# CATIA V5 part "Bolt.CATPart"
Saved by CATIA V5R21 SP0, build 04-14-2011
Part number: bolt
Bounding box of the stored display mesh (mm): x -86.603 to 86.603, y -100 to 100, z 0 to 450
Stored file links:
  D:\CATIA V5R21 E-RESOURCES\CATIA-V5R21\catia-v5r21-prt\c16-catia-v5r20-prt\Screw Joint-(Fig16-22)\CAT_V5R21_Bolt.CATPart
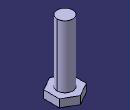
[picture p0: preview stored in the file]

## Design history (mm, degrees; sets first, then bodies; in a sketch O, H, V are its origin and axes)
Body1 (main body)
  Sketch1 on xy-plane, origin (0, 0, 0), H (1, 0, 0), V (0, 1, 0)
    point P1 (86.6025, -50)
    point P2 (86.6025, 50)
    point P3 (0, 100)
    point P4 (-86.6025, 50)
    point P5 (-86.6025, -50)
    point P6 (0, -100)
    point P7 (86.6025, 0)
    line L1 (86.6025, -50) -> (86.6025, 50)
    line L2 (86.6025, 50) -> (0, 100)
    line L3 (0, 100) -> (-86.6025, 50)
    line L4 (-86.6025, 50) -> (-86.6025, -50)
    line L5 (-86.6025, -50) -> (0, -100)
    line L6 (0, -100) -> (86.6025, -50)
    construction line L7 (0, 0) -> (86.6025, 0)
    construction circle A1 centre (0, 0) radius 100
    construction arc A2 centre (-86.6025, -50) radius 100 from (-86.6025, 50) to (0, -100) cw
    construction arc A3 centre (86.6025, 50) radius 100 from (0, 100) to (86.6025, -50) ccw
    radius A1 = 100
    horizontal: L7 H
    coincidence: A1 P1, A1 P2, A1 P3, A1 P4, A1 P5, A1 P6, A2 O, A3 O
    midpoint: P7 L1
    parallelism: L1 L4, L2 L5, L3 L6
    vertical: L4 V, L1 V
  Pad1: profile Sketch1, direction (0, 0, 1), length 50
  Sketch2 on end face of Pad1, origin (0, 0, 50), H (1, 0, 0), V (0, 1, 0)
    circle A1 centre (0, 0) radius 50
    point P1 (0, 50)
    radius A1 = 50
    coincidence: A1 P1, P1 V
  Pad2: profile Sketch2, direction (0, 0, 1), length 400
  Thread1: diameter 100, depth 400, pitch 1, on face of Pad2 from Sketch2.A1, from end face of Pad2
